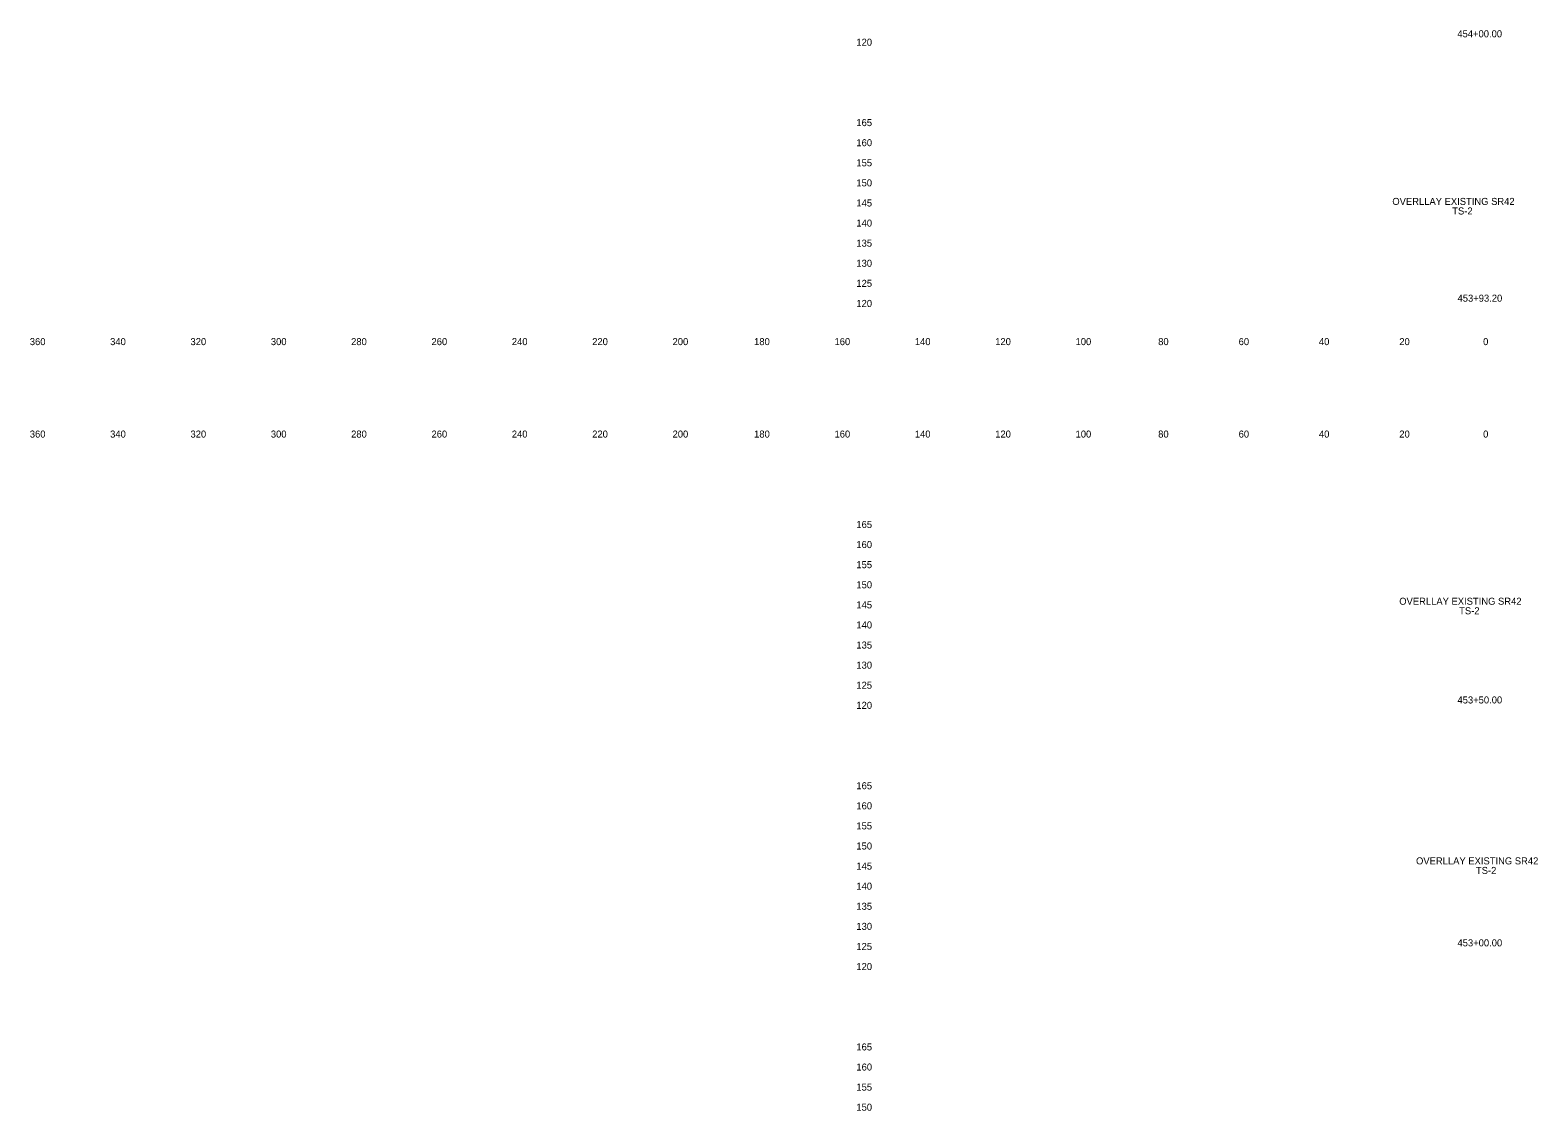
# Model space of a CAD drawing. Extents: x 21281 to 22024, y 6472 to 15198.
# Drawn here: x 21280.5 to 21655.7, y 6744.8 to 7013.7 of the extents above; entities that cross this region are included whole.
import ezdxf

# ---------------------------------------------------------------- set-up
doc = ezdxf.new("R2010")
doc.units = 0
for name, color, linetype in [('Draft_XS_Grid', 7, 'Continuous'), ('Draft_XS_Text', 7, 'Continuous'), ('SLOPE_STAKES_FILL', 7, 'Continuous')]:
    doc.layers.add(name, color=color, linetype=linetype)

msp = doc.modelspace()

# ---------------------------------------------------------------- texts
at = {"layer": 'Draft_XS_Grid'}
for s, p in [('  120  ', (21484.84, 7009.84)), ('  165  ', (21484.84, 6989.84)), ('  160  ', (21484.84, 6984.84)), ('  155  ', (21484.84, 6979.84)), ('  150  ', (21484.84, 6974.84)), ('  145  ', (21484.84, 6969.84)), ('  140  ', (21484.84, 6964.84)), ('  135  ', (21484.84, 6959.84)), ('  130  ', (21484.84, 6954.84)), ('  125  ', (21484.84, 6949.84)), ('  120  ', (21484.84, 6944.84)), ('  165  ', (21484.84, 6889.84)), ('  160  ', (21484.84, 6884.84)), ('  155  ', (21484.84, 6879.84)), ('  150  ', (21484.84, 6874.84)), ('  145  ', (21484.84, 6869.84)), ('  140  ', (21484.84, 6864.84)), ('  135  ', (21484.84, 6859.84)), ('  130  ', (21484.84, 6854.84)), ('  125  ', (21484.84, 6849.84)), ('  120  ', (21484.84, 6844.84)), ('  165  ', (21484.84, 6824.84)), ('  160  ', (21484.84, 6819.84)), ('  155  ', (21484.84, 6814.84)), ('  150  ', (21484.84, 6809.84)), ('  145  ', (21484.84, 6804.84)), ('  140  ', (21484.84, 6799.84)), ('  135  ', (21484.84, 6794.84)), ('  130  ', (21484.84, 6789.84)), ('  125  ', (21484.84, 6784.84)), ('  120  ', (21484.84, 6779.84)), ('  165  ', (21484.84, 6759.84)), ('  160  ', (21484.84, 6754.84)), ('  155  ', (21484.84, 6749.84)), ('  150  ', (21484.84, 6744.84))]:
    msp.add_text(s, height=1.75, dxfattribs=at).set_placement(p)
at = {"layer": 'Draft_XS_Text'}
for s, p in [('  360  ', (21279.14, 6935.34)), ('  340  ', (21299.13, 6935.34)), ('  320  ', (21319.13, 6935.34)), ('  300  ', (21339.13, 6935.34)), ('  280  ', (21359.1, 6935.34)), ('  260  ', (21379.11, 6935.34)), ('  240  ', (21399.1, 6935.34)), ('  220  ', (21419.1, 6935.34)), ('  200  ', (21439.1, 6935.34)), ('  180  ', (21459.39, 6935.34)), ('  160  ', (21479.4, 6935.34)), ('  140  ', (21499.39, 6935.34)), ('  120  ', (21519.39, 6935.34)), ('  100  ', (21539.39, 6935.34)), ('  80  ', (21559.95, 6935.34)), ('  60  ', (21579.97, 6935.34)), ('  40  ', (21599.95, 6935.34)), ('  20  ', (21619.95, 6935.34)), ('  0  ', (21640.81, 6935.34)), ('  0  ', (21640.81, 6935.34)), ('  360  ', (21279.14, 6912.34)), ('  340  ', (21299.13, 6912.34)), ('  320  ', (21319.13, 6912.34)), ('  300  ', (21339.13, 6912.34)), ('  280  ', (21359.1, 6912.34)), ('  260  ', (21379.11, 6912.34)), ('  240  ', (21399.1, 6912.34)), ('  220  ', (21419.1, 6912.34)), ('  200  ', (21439.1, 6912.34)), ('  180  ', (21459.39, 6912.34)), ('  160  ', (21479.4, 6912.34)), ('  140  ', (21499.39, 6912.34)), ('  120  ', (21519.39, 6912.34)), ('  100  ', (21539.39, 6912.34)), ('  80  ', (21559.95, 6912.34)), ('  60  ', (21579.97, 6912.34)), ('  40  ', (21599.95, 6912.34)), ('  20  ', (21619.95, 6912.34)), ('  0  ', (21640.81, 6912.34)), ('  0  ', (21640.81, 6912.34))]:
    msp.add_text(s, height=1.75, dxfattribs=at).set_placement(p)
at = {"layer": 'SLOPE_STAKES_FILL'}
for s, p in [('  454+00.00  ', (21634.4, 7011.94)), ('OVERLLAY EXISTING SR42', (21619.52, 6970.23)), ('TS-2', (21634.43, 6967.85)), ('  453+93.20  ', (21634.45, 6946.15)), ('OVERLLAY EXISTING SR42', (21621.24, 6870.74)), ('TS-2', (21636.15, 6868.37)), ('  453+50.00  ', (21634.43, 6846.18)), ('OVERLLAY EXISTING SR42', (21625.42, 6806.13)), ('TS-2', (21640.33, 6803.76)), ('  453+00.00  ', (21634.43, 6785.73))]:
    msp.add_text(s, height=1.75, dxfattribs=at).set_placement(p)

doc.saveas('drawing.dxf')
